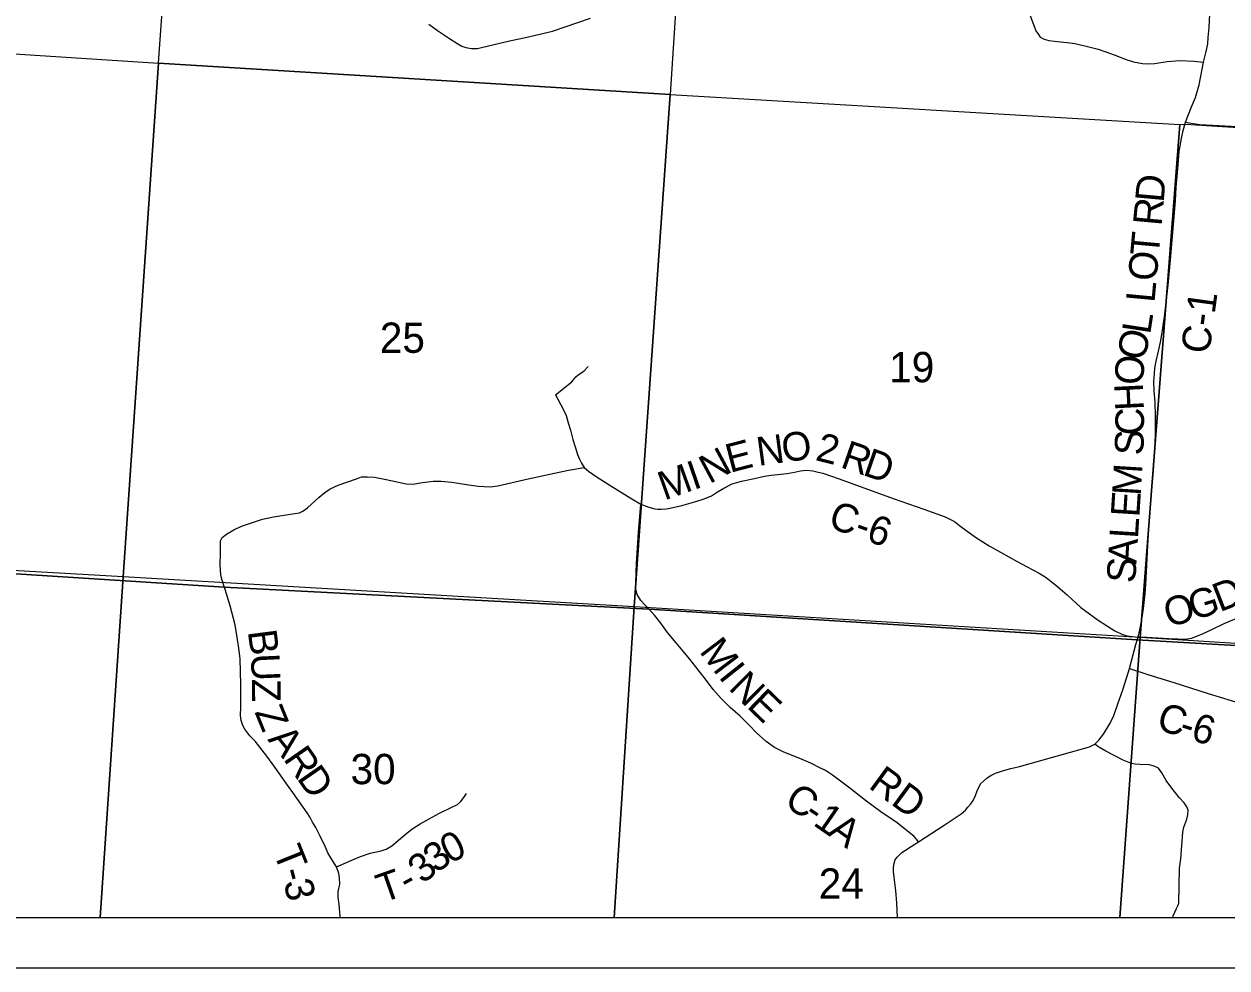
# Model space of a CAD drawing. Extents: x 0 to 34, y 0 to 22.
# Drawn here: x 4.807 to 7.19, y 14 to 15.87 of the extents above; entities that cross this region are included whole.
import ezdxf

# ---------------------------------------------------------------- set-up
doc = ezdxf.new("R2010")
doc.units = 0
for name, color, linetype in [('GM_X_Corporation', 7, 'Continuous'), ('GM_X_County_Road', 7, 'Continuous'), ('GM_X_County_Road_Text', 7, 'Continuous'), ('GM_X_Section_Text', 7, 'Continuous'), ('GM_X_Township_Road', 7, 'Continuous'), ('GM_X_Township_Road_Text', 7, 'Continuous'), ('GM_X_Township_Text', 7, 'Continuous'), ('SH_Data', 7, 'Continuous')]:
    doc.layers.add(name, color=color, linetype=linetype)

msp = doc.modelspace()

# ---------------------------------------------------------------- linework, layer by layer
at = {"layer": 'GM_X_Corporation'}
for points in [[(5.6294, 16.7819), (6.1525, 16.7497), (6.1454, 16.6317), (6.1179, 16.2098), (6.0868, 15.7303), (5.0732, 15.7926), (5.1457, 16.8107)], [(4.0444, 15.8589), (5.0732, 15.7926), (5.0032, 14.775), (3.9752, 14.8336)], [(5.0732, 15.7926), (6.0868, 15.7303), (6.016, 14.7151), (5.0032, 14.775)], [(6.0868, 15.7303), (7.097, 15.6707), (7.0183, 14.6543), (6.016, 14.7151)], [(7.097, 15.6707), (7.1079, 15.6712), (8.1117, 15.6084), (8.0192, 14.5919), (7.0183, 14.6543)], [(3.9197, 14.1), (8.9, 14.1), (8.9, 14.5351), (8.0587, 14.59), (7.0121, 14.6499), (6.0453, 14.7107), (5.2037, 14.7544), (4.6148, 14.7919), (3.9742, 14.8327)], [(3.9255, 14.1), (4.958, 14.1), (5.0032, 14.775), (3.9752, 14.8336)], [(4.958, 14.1), (5.9759, 14.1), (6.016, 14.7151), (5.0032, 14.775)], [(5.9759, 14.1), (6.9776, 14.1), (7.0183, 14.6543), (6.016, 14.7151)], [(6.9776, 14.1), (7.9827, 14.1), (8.0192, 14.5919), (7.0183, 14.6543)]]:
    msp.add_lwpolyline(points, close=True, dxfattribs=at)
at = {"layer": 'GM_X_County_Road'}
for points in [[(7.1436, 15.7943), (7.1457, 15.802), (7.1491, 15.8155), (7.1519, 15.8304), (7.1527, 15.843), (7.1545, 15.8633), (7.1562, 15.8902), (7.1573, 15.901), (7.1608, 15.9262), (7.1632, 15.9388), (7.1702, 15.9695), (7.1749, 15.9905), (7.1844, 16.0237), (7.2038, 16.0846)], [(5.7131, 15.8231), (5.7664, 15.8361), (5.8061, 15.8444), (5.8536, 15.8557), (5.9295, 15.8818)], [(6.7988, 15.8902), (6.8072, 15.8669), (6.8123, 15.8551), (6.8151, 15.8508), (6.8203, 15.844), (6.8277, 15.8402), (6.8375, 15.8375), (6.8483, 15.8358), (6.8604, 15.8347), (6.8733, 15.8335), (6.8886, 15.8314), (6.9085, 15.8269), (6.9349, 15.8202), (6.9503, 15.8148), (6.9666, 15.809), (6.9902, 15.7999), (7.0049, 15.7948), (7.0229, 15.7914), (7.0329, 15.7908), (7.0474, 15.792), (7.0714, 15.7954), (7.0964, 15.7976), (7.1251, 15.7963), (7.1436, 15.7943)], [(5.6088, 15.8699), (5.6263, 15.8573), (5.6496, 15.8414), (5.6665, 15.8307), (5.6741, 15.8258), (5.6819, 15.8232), (5.6937, 15.8211), (5.7055, 15.8213), (5.7131, 15.8231)], [(7.1077, 15.6755), (7.1197, 15.7056), (7.1279, 15.7245), (7.1353, 15.7494), (7.1436, 15.7943)], [(7.014, 14.6553), (7.0173, 14.67), (7.0211, 14.6902), (7.0249, 14.7118), (7.0277, 14.7409), (7.0294, 14.7597), (7.0334, 14.8368), (7.0359, 14.88), (7.038, 14.9083), (7.0442, 14.9849), (7.0473, 15.0276), (7.0484, 15.0563), (7.0488, 15.0936), (7.0475, 15.1211), (7.0456, 15.1432), (7.0452, 15.1612), (7.0463, 15.1778), (7.0473, 15.1884), (7.0501, 15.2019), (7.0545, 15.2219), (7.0581, 15.2395), (7.0629, 15.2665), (7.0642, 15.2777), (7.0663, 15.2901), (7.068, 15.307), (7.0735, 15.3528), (7.0781, 15.403), (7.0881, 15.5195), (7.0897, 15.5468), (7.0929, 15.5829), (7.0954, 15.6175), (7.0999, 15.6434), (7.103, 15.6587), (7.1077, 15.6755)], [(7.1077, 15.6755), (7.1191, 15.6738), (7.1364, 15.6707), (7.2111, 15.6666)], [(5.86, 15.1355), (5.8745, 15.1085), (5.8808, 15.0943), (5.8851, 15.0795), (5.8899, 15.0652), (5.8942, 15.047), (5.8989, 15.0324), (5.9035, 15.0169), (5.9074, 15.0076), (5.9116, 14.9997), (5.9165, 14.9914), (5.9252, 14.9844), (5.9426, 14.9722), (5.9547, 14.9643), (5.9694, 14.955), (6.0114, 14.9292), (6.0291, 14.9187)], [(6.0291, 14.9187), (6.0448, 14.9127), (6.0564, 14.9094), (6.0625, 14.9085), (6.0693, 14.9085), (6.08, 14.9096), (6.0895, 14.9115), (6.11, 14.9161), (6.1379, 14.924), (6.1541, 14.929), (6.1687, 14.9351), (6.1786, 14.9419), (6.1934, 14.9501), (6.2101, 14.9588), (6.2282, 14.964), (6.254, 14.9693), (6.2738, 14.9739), (6.2871, 14.9763), (6.319, 14.9792), (6.3333, 14.982), (6.3449, 14.9849), (6.3574, 14.986), (6.3696, 14.9847), (6.38, 14.9824), (6.3897, 14.9799), (6.4215, 14.9691), (6.529, 14.9298), (6.5895, 14.9089), (6.6317, 14.8935), (6.6505, 14.8845), (6.6602, 14.8764), (6.6752, 14.8653), (6.694, 14.852), (6.7191, 14.8361), (6.7411, 14.8237), (6.7742, 14.8053), (6.793, 14.7954), (6.8177, 14.7817), (6.8316, 14.7732), (6.842, 14.7652), (6.8512, 14.7585), (6.8593, 14.7509), (6.8732, 14.7388), (6.9004, 14.7141), (6.9346, 14.689), (6.9678, 14.6675), (6.9815, 14.661), (6.9918, 14.6582), (7.014, 14.6553)], [(6.0508, 14.7046), (6.0455, 14.7102), (6.029, 14.7277), (6.0216, 14.7395), (6.0192, 14.7497), (6.0188, 14.7627), (6.0206, 14.8016), (6.0242, 14.8623), (6.0291, 14.9187)], [(6.5791, 14.2497), (6.5745, 14.2559), (6.5699, 14.2609), (6.5539, 14.2737), (6.5366, 14.2873), (6.5046, 14.3094), (6.474, 14.3318), (6.4431, 14.3564), (6.4083, 14.3821), (6.3949, 14.3909), (6.3919, 14.3924), (6.3848, 14.3959), (6.366, 14.4053), (6.3438, 14.4149), (6.319, 14.4251), (6.3112, 14.4283), (6.2937, 14.4369), (6.2773, 14.4487), (6.2579, 14.4656), (6.2443, 14.4804), (6.2256, 14.4986), (6.2062, 14.5158), (6.188, 14.5335), (6.1724, 14.5517), (6.1592, 14.5695), (6.1263, 14.6114), (6.0817, 14.6646), (6.0686, 14.6828), (6.0562, 14.6989), (6.0508, 14.7046)], [(6.9967, 14.5932), (7.0097, 14.6405), (7.011, 14.6449)], [(7.011, 14.6449), (7.0123, 14.6494), (7.014, 14.6553)], [(6.5791, 14.2497), (6.63, 14.2825), (6.6634, 14.3053), (6.672, 14.3124), (6.6769, 14.3182), (6.6826, 14.325), (6.6872, 14.3318), (6.692, 14.3417), (6.695, 14.3511), (6.6983, 14.3581), (6.7027, 14.3654), (6.7082, 14.3703), (6.7151, 14.3763), (6.7223, 14.3809), (6.7318, 14.3855), (6.7454, 14.3903), (6.7621, 14.3953), (6.7788, 14.3993), (6.9179, 14.438), (6.9284, 14.4431), (6.9364, 14.4515), (6.9453, 14.4633), (6.959, 14.4851), (6.9658, 14.4998), (6.9734, 14.5211), (6.9847, 14.5527), (6.9967, 14.5932)], [(6.9967, 14.5932), (7.0353, 14.5808), (7.0847, 14.5656), (7.1528, 14.5436), (7.2219, 14.5223)], [(6.5375, 14.1), (6.5362, 14.1283), (6.5341, 14.1532), (6.5309, 14.1798), (6.5296, 14.1911), (6.5295, 14.1989), (6.5305, 14.2075), (6.5326, 14.2139), (6.5364, 14.2197), (6.5399, 14.223), (6.546, 14.2285), (6.5534, 14.2336), (6.5647, 14.2405), (6.5791, 14.2497)]]:
    msp.add_lwpolyline(points, dxfattribs=at)
at = {"layer": 'GM_X_Township_Road'}
for points in [[(5.86, 15.1355), (5.8919, 15.1612), (5.9004, 15.1711), (5.905, 15.1751), (5.9158, 15.1822), (5.9243, 15.1916)], [(5.1982, 14.7728), (5.1966, 14.7785), (5.1956, 14.7987), (5.1959, 14.8208), (5.1961, 14.8366), (5.1963, 14.846), (5.1997, 14.8524), (5.2083, 14.8596), (5.2227, 14.8676), (5.2378, 14.8752), (5.2637, 14.8836), (5.2793, 14.8891), (5.3014, 14.8939), (5.3263, 14.8975), (5.3435, 14.8999), (5.3524, 14.9016), (5.3595, 14.9051), (5.3688, 14.9115), (5.3918, 14.9324), (5.4026, 14.9419), (5.4133, 14.9488), (5.4291, 14.9564), (5.4657, 14.9689), (5.4754, 14.9726), (5.4873, 14.973), (5.5011, 14.9724), (5.5181, 14.9691), (5.5401, 14.9641), (5.5546, 14.9608), (5.5643, 14.9587), (5.5775, 14.9583), (5.5966, 14.9616), (5.6175, 14.9645), (5.6332, 14.9645), (5.6548, 14.9626), (5.6834, 14.9579), (5.7068, 14.9542), (5.7302, 14.9531), (5.7459, 14.9552), (5.8058, 14.9689), (5.8577, 14.9802), (5.8853, 14.9863), (5.9165, 14.9914)], [(5.2344, 14.618), (5.2316, 14.6381), (5.2251, 14.6798), (5.2151, 14.7174), (5.2052, 14.7496), (5.2039, 14.7538), (5.1985, 14.7719), (5.1982, 14.7728)], [(7.1416, 14.662), (7.1598, 14.6703), (7.1845, 14.6822), (7.2506, 14.7098)], [(7.014, 14.6553), (7.0313, 14.6551), (7.0748, 14.6529), (7.0927, 14.6517), (7.1075, 14.6515), (7.1203, 14.6533), (7.1353, 14.6591), (7.1416, 14.662)], [(5.433, 14.1), (5.433, 14.1019), (5.4316, 14.1263), (5.429, 14.1398), (5.4294, 14.1515), (5.4328, 14.1661), (5.4318, 14.1786), (5.4304, 14.1872), (5.4261, 14.2002), (5.4148, 14.2179), (5.409, 14.2278), (5.404, 14.2393), (5.3937, 14.2611), (5.3851, 14.2779), (5.3786, 14.2887), (5.3738, 14.2978), (5.3676, 14.3071), (5.3395, 14.3477), (5.3307, 14.3591), (5.304, 14.398), (5.2879, 14.4198), (5.2743, 14.4376), (5.2647, 14.4491), (5.2546, 14.4599), (5.2443, 14.4728), (5.2407, 14.4805), (5.2373, 14.4901), (5.2359, 14.5002), (5.2362, 14.5172), (5.2364, 14.562), (5.2352, 14.6119), (5.2344, 14.618)], [(7.083, 14.1), (7.0838, 14.1029), (7.0902, 14.1174), (7.0928, 14.1229), (7.0945, 14.1283), (7.0962, 14.1974), (7.0985, 14.2164), (7.1026, 14.2692), (7.1043, 14.2786), (7.1107, 14.2947), (7.1124, 14.3031), (7.1132, 14.3122), (7.1106, 14.319), (7.1053, 14.3269), (7.0953, 14.3373), (7.0806, 14.356), (7.0698, 14.3716), (7.0611, 14.3865), (7.0542, 14.3956), (7.0457, 14.3997), (7.0359, 14.402), (7.0184, 14.4031), (7.0083, 14.4037), (7.0007, 14.4051), (6.9944, 14.4074), (6.9843, 14.4115), (6.9501, 14.4295), (6.9375, 14.4365), (6.9334, 14.4394), (6.9284, 14.4431)], [(5.4261, 14.2002), (5.4608, 14.2155), (5.4733, 14.2208), (5.493, 14.2273), (5.5148, 14.2318), (5.5244, 14.235), (5.5357, 14.2417), (5.5661, 14.2675), (5.5774, 14.2765), (5.5918, 14.2857), (5.6093, 14.2952), (5.6289, 14.3062), (5.6556, 14.3188), (5.6657, 14.324), (5.6719, 14.3289), (5.678, 14.3379), (5.6834, 14.3452)]]:
    msp.add_lwpolyline(points, dxfattribs=at)
at = {"layer": 'GM_X_Township_Text'}
msp.add_lwpolyline([(3.9742, 14.8327), (4.6148, 14.7919), (5.2037, 14.7544), (6.0453, 14.7107), (7.0121, 14.6499), (8.0587, 14.59), (8.9, 14.5351)], dxfattribs=at)
at = {"layer": 'SH_Data'}
for p, q in [((2.1, 14.1), (8.9, 14.1)), ((2, 14), (9, 14))]:
    msp.add_line(p, q, dxfattribs=at)

# ---------------------------------------------------------------- texts
at = {"layer": 'GM_X_County_Road_Text'}
for s, height, rotation, p in [('D', 0.0568, 84.7947, (7.0645, 15.5151)), ('R', 0.0568, 84.797, (7.0603, 15.4686)), ('T', 0.0568, 84.7943, (7.0548, 15.4089)), ('O', 0.0568, 84.7966, (7.0503, 15.3591)), ('L', 0.0568, 84.7508, (7.0464, 15.3167)), ('C-1', 0.05682, 82.2609, (7.1549, 15.2148)), ('L', 0.0568, 81.3146, (7.0379, 15.2536)), ('O', 0.0568, 78.0449, (7.0269, 15.2012)), ('O', 0.0568, 85.4418, (7.0232, 15.1533)), ('H', 0.0568, 92.911, (7.0258, 15.1053)), ('C', 0.0568, 89.6823, (7.0256, 15.0551)), ('O', 0.0568, 8.0057, (6.3118, 15.0012)), ('S', 0.0568, 87.5722, (7.0239, 15.0145)), ('E', 0.0568, 14.5778, (6.2054, 14.9805)), ('N', 0.0568, 7.669, (6.2618, 14.9945)), ('2', 0.0568, 345.9764, (6.3729, 15.0063)), ('R', 0.0568, 340.8159, (6.4221, 14.9925)), ('N', 0.0568, 28.3454, (6.1647, 14.9581)), ('D', 0.0568, 340.7909, (6.4662, 14.9772)), ('M', 0.0568, 19.7063, (6.0755, 14.9257)), ('I', 0.0568, 18.9681, (6.1334, 14.9465)), ('M', 0.0568, 86.455, (7.019, 14.9343)), ('C-6', 0.05682, 340.4078, (6.3975, 14.8738)), ('E', 0.0568, 86.4277, (7.0164, 14.8919)), ('L', 0.0568, 86.4303, (7.0137, 14.8494)), ('A', 0.0568, 86.4278, (7.0106, 14.7995)), ('S', 0.0568, 86.4293, (7.0082, 14.7613)), ('M', 0.0568, 307.1919, (6.1433, 14.6268)), ('I', 0.0568, 308.4815, (6.1814, 14.5766)), ('N', 0.0568, 315.2972, (6.2008, 14.5529)), ('E', 0.0568, 316.0099, (6.2369, 14.5172)), ('C', 0.0568, 342.1822, (7.0478, 14.4737)), ('6', 0.0568, 343.8815, (7.1163, 14.4519)), ('-', 0.0568, 342.5862, (7.0927, 14.4593)), ('RD', 0.05682, 323.7707, (6.4778, 14.358)), ('C', 0.0568, 325.8975, (6.3103, 14.3234)), ('-', 0.0568, 325.7882, (6.3489, 14.2973)), ('1', 0.0568, 325.4872, (6.3681, 14.2842)), ('A', 0.0568, 324.4183, (6.3967, 14.2645))]:
    msp.add_text(s, height=height, rotation=rotation, dxfattribs=at).set_placement(p)
at = {"layer": 'GM_X_Section_Text'}
for s, p in [('25', (5.5119, 15.2185)), ('19', (6.521, 15.1602)), ('30', (5.4539, 14.364)), ('24', (6.3814, 14.1372))]:
    msp.add_text(s, height=0.06, rotation=0, dxfattribs=at).set_placement(p)
at = {"layer": 'GM_X_Township_Road_Text'}
for s, rotation, p in [('G', 16.859, (7.1233, 14.6882)), ('D', 21.3985, (7.1758, 14.7043)), ('O', 16.074, (7.0744, 14.6741)), ('B', 277.4344, (5.2502, 14.6669)), ('U', 272.4979, (5.2561, 14.6219)), ('Z', 270.4736, (5.2583, 14.5725)), ('Z', 292.1673, (5.2632, 14.5071)), ('A', 309.0911, (5.2886, 14.452)), ('R', 304.8517, (5.3194, 14.4141)), ('D', 304.7742, (5.3461, 14.3758)), ('3', 34.7957, (5.6231, 14.1866)), ('0', 27.3191, (5.6501, 14.2055)), ('T', 291.8949, (5.2999, 14.2296)), ('3', 40.0342, (5.5973, 14.1649)), ('-', 284.7803, (5.3151, 14.192)), ('T', 19.3782, (5.5175, 14.1285)), ('-', 28.836, (5.5669, 14.1468)), ('3', 282.8788, (5.321, 14.1699))]:
    msp.add_text(s, height=0.0568, rotation=rotation, dxfattribs=at).set_placement(p)

doc.saveas('drawing.dxf')
